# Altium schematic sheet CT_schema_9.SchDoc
size 278 x 170 mm
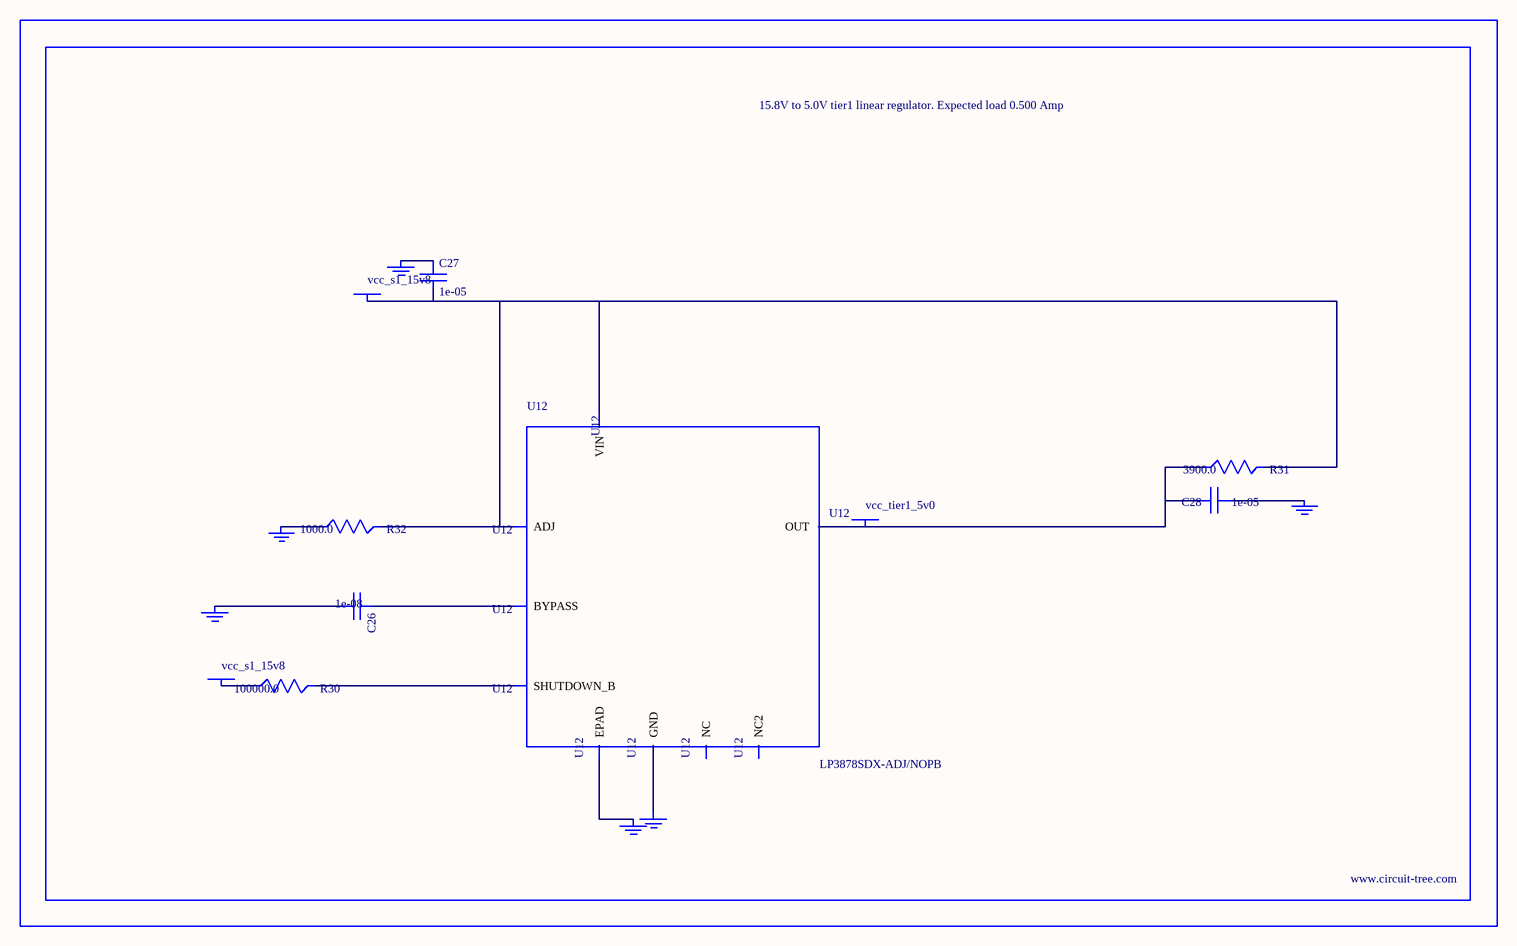
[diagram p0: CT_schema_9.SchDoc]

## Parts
BORDER8  (no value)
C26  1e-08  [C0402]
C27  1e-05  [C1210]
C28  1e-05  [C1210]
GND_INSTANCE_8_0  (no value)
GND_INSTANCE_8_1  (no value)
GND_INSTANCE_8_2  (no value)
GND_INSTANCE_8_3  (no value)
GND_INSTANCE_8_4  (no value)
GND_INSTANCE_8_5  (no value)
POWER_INSTANCE_8_0  vcc_s1_15v8
POWER_INSTANCE_8_1  vcc_s1_15v8
POWER_INSTANCE_8_2  vcc_tier1_5v0
R30  100000.0  [R0603]
R31  3900.0  [R0603]
R32  1000.0  [R0603]
U12  LP3878SDX-ADJ/NOPB  [WSON-8]

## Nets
NetC26_1: C26.1 U12.1(BYPASS)
NetC26_2: C26.2 GND_INSTANCE_8_0.0(GND)
NetC27_1: C27.1 GND_INSTANCE_8_1.0(GND)
NetC27_2: C27.2 POWER_INSTANCE_8_0.0(PWR) R31.2 R32.2 U12.4(VIN) U12.6(ADJ)
NetC28_1: C28.1 GND_INSTANCE_8_2.0(GND)
NetC28_2: C28.2 POWER_INSTANCE_8_2.0(PWR) R31.1 U12.5(OUT)
NetGND_INSTANCE_8_3_0: GND_INSTANCE_8_3.0(GND) R32.1
NetGND_INSTANCE_8_4_0: GND_INSTANCE_8_4.0(GND) U12.PAD(EPAD)
NetGND_INSTANCE_8_5_0: GND_INSTANCE_8_5.0(GND) U12.3(GND)
NetPOWER_INSTANCE_8_1_0: POWER_INSTANCE_8_1.0(PWR) R30.1
NetR30_2: R30.2 U12.8(SHUTDOWN_B)

Not connected (* = marked no-connect by the designer): U12 2(NC) 7(NC2)

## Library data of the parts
BORDER8 = BORDER_PAGE8
C26 = C0402C103K3RAC
C27 = C1210C106K5PACTU
C28 = GRM32DR61E106MA12L
GND_INSTANCE_8_0-GND_INSTANCE_8_5 = GND
POWER_INSTANCE_8_0-POWER_INSTANCE_8_2 = PWR
R30 = RC0603JR-07100KL
R31 = RC0603JR-073K9L
R32 = RC0603JR-071KL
